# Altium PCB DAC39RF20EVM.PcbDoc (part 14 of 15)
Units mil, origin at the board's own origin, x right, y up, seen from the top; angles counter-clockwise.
Board outline 6200 x 2716.54 mil, 16 copper layers (Top Layer, L2 GND, L3 PWR, L4 GND, L5 PWR, L6 GND, L7 SIG, L8 GND, L9 GND, L10 SIG, L11 GND, L12 PWR, L13 GND, L14 PWR, L15 GND, Bottom Layer), stack 76.97 mil thick; 766 components, 495 nets, 3414 pads, 2373 vias.
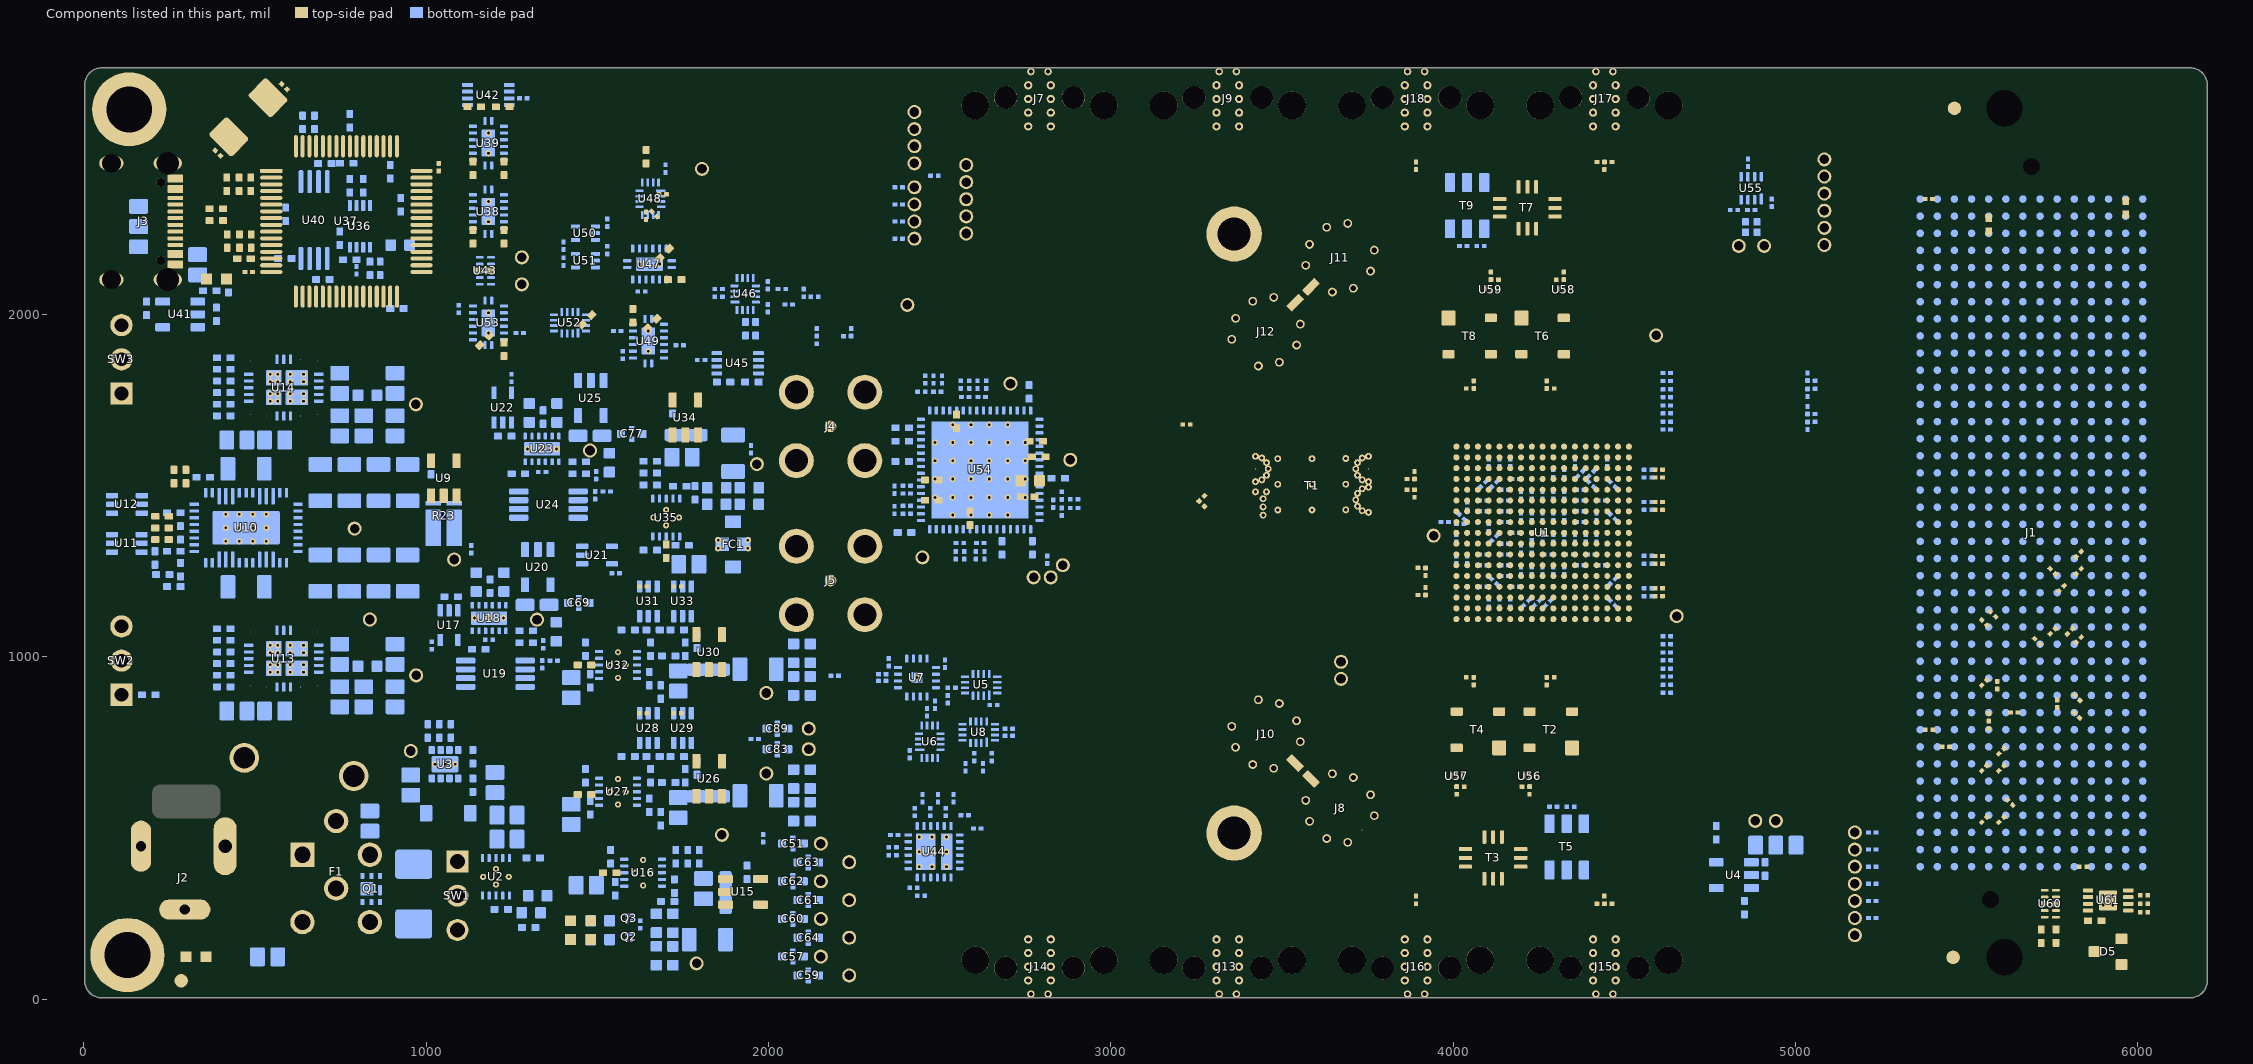
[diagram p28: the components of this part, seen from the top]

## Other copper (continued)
L9 GND:
  pour cut-out: 3434.48,1511.7 ccw(c3422.48,1511.7) 3422.48,1523.7 ccw(c3422.48,1511.7) 3410.48,1511.7 ccw(c3422.48,1511.7) 3422.48,1499.7 ccw(c3422.48,1511.7)
  pour cut-out: 3452.98,1516.66 ccw(c3440.98,1516.66) 3440.98,1528.66 ccw(c3440.98,1516.66) 3428.98,1516.66 ccw(c3440.98,1516.66) 3440.98,1504.66 ccw(c3440.98,1516.66)
  pour cut-out: 3466.52,1530.2 ccw(c3454.52,1530.2) 3454.52,1542.2 ccw(c3454.52,1530.2) 3442.52,1530.2 ccw(c3454.52,1530.2) 3454.52,1518.2 ccw(c3454.52,1530.2)
  pour cut-out: 3471.48,1548.7 ccw(c3459.48,1548.7) 3459.48,1560.7 ccw(c3459.48,1548.7) 3447.48,1548.7 ccw(c3459.48,1548.7) 3459.48,1536.7 ccw(c3459.48,1548.7)
  pour cut-out: 3466.52,1567.2 ccw(c3454.52,1567.2) 3454.52,1579.2 ccw(c3454.52,1567.2) 3442.52,1567.2 ccw(c3454.52,1567.2) 3454.52,1555.2 ccw(c3454.52,1567.2)
  pour cut-out: 3452.98,1580.74 ccw(c3440.98,1580.74) 3440.98,1592.74 ccw(c3440.98,1580.74) 3428.98,1580.74 ccw(c3440.98,1580.74) 3440.98,1568.74 ccw(c3440.98,1580.74)
  pour cut-out: 3434.48,1585.7 ccw(c3422.48,1585.7) 3422.48,1597.7 ccw(c3422.48,1585.7) 3410.48,1585.7 ccw(c3422.48,1585.7) 3422.48,1573.7 ccw(c3422.48,1585.7)
  pour cut-out: 3740.48,1495.7 ccw(c3752.48,1495.7) 3752.48,1483.7 ccw(c3752.48,1495.7) 3764.48,1495.7 ccw(c3752.48,1495.7) 3752.48,1507.7 ccw(c3752.48,1495.7)
  pour cut-out: 3721.98,1490.74 ccw(c3733.98,1490.74) 3733.98,1478.74 ccw(c3733.98,1490.74) 3745.98,1490.74 ccw(c3733.98,1490.74) 3733.98,1502.74 ccw(c3733.98,1490.74)
  pour cut-out: 3708.43,1477.2 ccw(c3720.43,1477.2) 3720.43,1465.2 ccw(c3720.43,1477.2) 3732.43,1477.2 ccw(c3720.43,1477.2) 3720.43,1489.2 ccw(c3720.43,1477.2)
  pour cut-out: 3703.48,1458.7 ccw(c3715.48,1458.7) 3715.48,1446.7 ccw(c3715.48,1458.7) 3727.48,1458.7 ccw(c3715.48,1458.7) 3715.48,1470.7 ccw(c3715.48,1458.7)
  pour cut-out: 3708.43,1440.2 ccw(c3720.43,1440.2) 3720.43,1428.2 ccw(c3720.43,1440.2) 3732.43,1440.2 ccw(c3720.43,1440.2) 3720.43,1452.2 ccw(c3720.43,1440.2)
  pour cut-out: 3721.98,1426.66 ccw(c3733.98,1426.66) 3733.98,1414.66 ccw(c3733.98,1426.66) 3745.98,1426.66 ccw(c3733.98,1426.66) 3733.98,1438.66 ccw(c3733.98,1426.66)
  pour cut-out: 3740.48,1421.7 ccw(c3752.48,1421.7) 3752.48,1409.7 ccw(c3752.48,1421.7) 3764.48,1421.7 ccw(c3752.48,1421.7) 3752.48,1433.7 ccw(c3752.48,1421.7)
  pour cut-out: 3740.48,1511.7 ccw(c3752.48,1511.7) 3752.48,1499.7 ccw(c3752.48,1511.7) 3764.48,1511.7 ccw(c3752.48,1511.7) 3752.48,1523.7 ccw(c3752.48,1511.7)
  pour cut-out: 3721.98,1516.66 ccw(c3733.98,1516.66) 3733.98,1504.66 ccw(c3733.98,1516.66) 3745.98,1516.66 ccw(c3733.98,1516.66) 3733.98,1528.66 ccw(c3733.98,1516.66)
  pour cut-out: 3708.43,1530.2 ccw(c3720.43,1530.2) 3720.43,1518.2 ccw(c3720.43,1530.2) 3732.43,1530.2 ccw(c3720.43,1530.2) 3720.43,1542.2 ccw(c3720.43,1530.2)
  pour cut-out: 3703.48,1548.7 ccw(c3715.48,1548.7) 3715.48,1536.7 ccw(c3715.48,1548.7) 3727.48,1548.7 ccw(c3715.48,1548.7) 3715.48,1560.7 ccw(c3715.48,1548.7)
  pour cut-out: 3708.43,1567.2 ccw(c3720.43,1567.2) 3720.43,1555.2 ccw(c3720.43,1567.2) 3732.43,1567.2 ccw(c3720.43,1567.2) 3720.43,1579.2 ccw(c3720.43,1567.2)
  pour cut-out: 3721.98,1580.74 ccw(c3733.98,1580.74) 3733.98,1568.74 ccw(c3733.98,1580.74) 3745.98,1580.74 ccw(c3733.98,1580.74) 3733.98,1592.74 ccw(c3733.98,1580.74)
  pour cut-out: 3740.48,1585.7 ccw(c3752.48,1585.7) 3752.48,1573.7 ccw(c3752.48,1585.7) 3764.48,1585.7 ccw(c3752.48,1585.7) 3752.48,1597.7 ccw(c3752.48,1585.7)
  pour cut-out: 3998.03,1456.46 ccw(c4009.03,1456.46) 4009.03,1445.46 ccw(c4009.03,1456.46) 4020.03,1456.46 ccw(c4009.03,1456.46) 4009.03,1467.46 ccw(c4009.03,1456.46)
  pour cut-out: 4029.52,1487.95 ccw(c4040.52,1487.95) 4040.52,1476.95 ccw(c4040.52,1487.95) 4051.52,1487.95 ccw(c4040.52,1487.95) 4040.52,1498.95 ccw(c4040.52,1487.95)
  pour cut-out: 4029.52,1519.45 ccw(c4040.52,1519.45) 4040.52,1508.45 ccw(c4040.52,1519.45) 4051.52,1519.45 ccw(c4040.52,1519.45) 4040.52,1530.45 ccw(c4040.52,1519.45)
  pour cut-out: 3998.03,1550.94 ccw(c4009.03,1550.94) 4009.03,1539.94 ccw(c4009.03,1550.94) 4020.03,1550.94 ccw(c4009.03,1550.94) 4009.03,1561.94 ccw(c4009.03,1550.94)
  pour cut-out: 4218.5,1613.94 ccw(c4229.5,1613.94) 4229.5,1602.94 ccw(c4229.5,1613.94) 4240.5,1613.94 ccw(c4229.5,1613.94) 4229.5,1624.94 ccw(c4229.5,1613.94)
  pour cut-out: 4155.51,1613.94 ccw(c4166.51,1613.94) 4166.51,1602.94 ccw(c4166.51,1613.94) 4177.51,1613.94 ccw(c4166.51,1613.94) 4166.51,1624.94 ccw(c4166.51,1613.94)
  pour cut-out: 4092.52,1613.94 ccw(c4103.52,1613.94) 4103.52,1602.94 ccw(c4103.52,1613.94) 4114.52,1613.94 ccw(c4103.52,1613.94) 4103.52,1624.94 ccw(c4103.52,1613.94)
  pour cut-out: 4218.5,1110 ccw(c4229.5,1110) 4229.5,1099 ccw(c4229.5,1110) 4240.5,1110 ccw(c4229.5,1110) 4229.5,1121 ccw(c4229.5,1110)
  pour cut-out: 4155.51,1110 ccw(c4166.51,1110) 4166.51,1099 ccw(c4166.51,1110) 4177.51,1110 ccw(c4166.51,1110) 4166.51,1121 ccw(c4166.51,1110)
  pour cut-out: 4092.52,1110 ccw(c4103.52,1110) 4103.52,1099 ccw(c4103.52,1110) 4114.52,1110 ccw(c4103.52,1110) 4103.52,1121 ccw(c4103.52,1110)
  pour cut-out: 4408.51,157.8 cw(c4408.51,174.8) 4391.51,174.8 cw(c4408.51,174.8) 4408.51,191.8 cw(c4408.51,174.8) 4425.51,174.8 cw(c4408.51,174.8)
  pour cut-out: 4408.51,117.8 cw(c4408.51,134.8) 4391.51,134.8 cw(c4408.51,134.8) 4408.51,151.8 cw(c4408.51,134.8) 4425.51,134.8 cw(c4408.51,134.8)
  pour cut-out: 4408.51,77.8 cw(c4408.51,94.8) 4391.51,94.8 cw(c4408.51,94.8) 4408.51,111.8 cw(c4408.51,94.8) 4425.51,94.8 cw(c4408.51,94.8)
  pour cut-out: 4408.51,37.8 cw(c4408.51,54.8) 4391.51,54.8 cw(c4408.51,54.8) 4408.51,71.8 cw(c4408.51,54.8) 4425.51,54.8 cw(c4408.51,54.8)
  pour cut-out: 4416.51,-2.2 cw(c4416.51,14.8) 4399.51,14.8 cw(c4416.51,14.8) 4416.51,31.8 cw(c4416.51,14.8) 4433.51,14.8 cw(c4416.51,14.8)
  pour cut-out: 4466.51,-2.2 cw(c4466.51,14.8) 4449.51,14.8 cw(c4466.51,14.8) 4466.51,31.8 cw(c4466.51,14.8) 4483.51,14.8 cw(c4466.51,14.8)
  pour cut-out: 4474.51,37.8 cw(c4474.51,54.8) 4457.51,54.8 cw(c4474.51,54.8) 4474.51,71.8 cw(c4474.51,54.8) 4491.51,54.8 cw(c4474.51,54.8)
  pour cut-out: 4474.51,77.8 cw(c4474.51,94.8) 4457.51,94.8 cw(c4474.51,94.8) 4474.51,111.8 cw(c4474.51,94.8) 4491.51,94.8 cw(c4474.51,94.8)
  pour cut-out: 4474.51,157.8 cw(c4474.51,174.8) 4457.51,174.8 cw(c4474.51,174.8) 4474.51,191.8 cw(c4474.51,174.8) 4491.51,174.8 cw(c4474.51,174.8)
  pour cut-out: 4474.51,117.8 cw(c4474.51,134.8) 4457.51,134.8 cw(c4474.51,134.8) 4474.51,151.8 cw(c4474.51,134.8) 4491.51,134.8 cw(c4474.51,134.8)
  pour cut-out: 3858.51,157.8 cw(c3858.51,174.8) 3841.51,174.8 cw(c3858.51,174.8) 3858.51,191.8 cw(c3858.51,174.8) 3875.51,174.8 cw(c3858.51,174.8)
  pour cut-out: 3858.51,117.8 cw(c3858.51,134.8) 3841.51,134.8 cw(c3858.51,134.8) 3858.51,151.8 cw(c3858.51,134.8) 3875.51,134.8 cw(c3858.51,134.8)
  pour cut-out: 3858.51,77.8 cw(c3858.51,94.8) 3841.51,94.8 cw(c3858.51,94.8) 3858.51,111.8 cw(c3858.51,94.8) 3875.51,94.8 cw(c3858.51,94.8)
  pour cut-out: 3858.51,37.8 cw(c3858.51,54.8) 3841.51,54.8 cw(c3858.51,54.8) 3858.51,71.8 cw(c3858.51,54.8) 3875.51,54.8 cw(c3858.51,54.8)
  pour cut-out: 3866.51,-2.2 cw(c3866.51,14.8) 3849.51,14.8 cw(c3866.51,14.8) 3866.51,31.8 cw(c3866.51,14.8) 3883.51,14.8 cw(c3866.51,14.8)
  pour cut-out: 3916.51,-2.2 cw(c3916.51,14.8) 3899.51,14.8 cw(c3916.51,14.8) 3916.51,31.8 cw(c3916.51,14.8) 3933.51,14.8 cw(c3916.51,14.8)
  pour cut-out: 3924.51,37.8 cw(c3924.51,54.8) 3907.51,54.8 cw(c3924.51,54.8) 3924.51,71.8 cw(c3924.51,54.8) 3941.51,54.8 cw(c3924.51,54.8)
  pour cut-out: 3924.51,77.8 cw(c3924.51,94.8) 3907.51,94.8 cw(c3924.51,94.8) 3924.51,111.8 cw(c3924.51,94.8) 3941.51,94.8 cw(c3924.51,94.8)
  pour cut-out: 3924.51,157.8 cw(c3924.51,174.8) 3907.51,174.8 cw(c3924.51,174.8) 3924.51,191.8 cw(c3924.51,174.8) 3941.51,174.8 cw(c3924.51,174.8)
  pour cut-out: 3924.51,117.8 cw(c3924.51,134.8) 3907.51,134.8 cw(c3924.51,134.8) 3924.51,151.8 cw(c3924.51,134.8) 3941.51,134.8 cw(c3924.51,134.8)
  pour cut-out: 3308.51,157.8 cw(c3308.51,174.8) 3291.51,174.8 cw(c3308.51,174.8) 3308.51,191.8 cw(c3308.51,174.8) 3325.51,174.8 cw(c3308.51,174.8)
  pour cut-out: 3308.51,117.8 cw(c3308.51,134.8) 3291.51,134.8 cw(c3308.51,134.8) 3308.51,151.8 cw(c3308.51,134.8) 3325.51,134.8 cw(c3308.51,134.8)
  pour cut-out: 3308.51,77.8 cw(c3308.51,94.8) 3291.51,94.8 cw(c3308.51,94.8) 3308.51,111.8 cw(c3308.51,94.8) 3325.51,94.8 cw(c3308.51,94.8)
  pour cut-out: 3308.51,37.8 cw(c3308.51,54.8) 3291.51,54.8 cw(c3308.51,54.8) 3308.51,71.8 cw(c3308.51,54.8) 3325.51,54.8 cw(c3308.51,54.8)
  pour cut-out: 3316.51,-2.2 cw(c3316.51,14.8) 3299.51,14.8 cw(c3316.51,14.8) 3316.51,31.8 cw(c3316.51,14.8) 3333.51,14.8 cw(c3316.51,14.8)
  pour cut-out: 3366.51,-2.2 cw(c3366.51,14.8) 3349.51,14.8 cw(c3366.51,14.8) 3366.51,31.8 cw(c3366.51,14.8) 3383.51,14.8 cw(c3366.51,14.8)
  pour cut-out: 3374.51,37.8 cw(c3374.51,54.8) 3357.51,54.8 cw(c3374.51,54.8) 3374.51,71.8 cw(c3374.51,54.8) 3391.51,54.8 cw(c3374.51,54.8)
  pour cut-out: 3374.51,77.8 cw(c3374.51,94.8) 3357.51,94.8 cw(c3374.51,94.8) 3374.51,111.8 cw(c3374.51,94.8) 3391.51,94.8 cw(c3374.51,94.8)
  pour cut-out: 3374.51,157.8 cw(c3374.51,174.8) 3357.51,174.8 cw(c3374.51,174.8) 3374.51,191.8 cw(c3374.51,174.8) 3391.51,174.8 cw(c3374.51,174.8)
  pour cut-out: 3374.51,117.8 cw(c3374.51,134.8) 3357.51,134.8 cw(c3374.51,134.8) 3374.51,151.8 cw(c3374.51,134.8) 3391.51,134.8 cw(c3374.51,134.8)
  pour cut-out: 2758.51,157.8 cw(c2758.51,174.8) 2741.51,174.8 cw(c2758.51,174.8) 2758.51,191.8 cw(c2758.51,174.8) 2775.51,174.8 cw(c2758.51,174.8)
  pour cut-out: 2758.51,117.8 cw(c2758.51,134.8) 2741.51,134.8 cw(c2758.51,134.8) 2758.51,151.8 cw(c2758.51,134.8) 2775.51,134.8 cw(c2758.51,134.8)
  pour cut-out: 2758.51,77.8 cw(c2758.51,94.8) 2741.51,94.8 cw(c2758.51,94.8) 2758.51,111.8 cw(c2758.51,94.8) 2775.51,94.8 cw(c2758.51,94.8)
  pour cut-out: 2758.51,37.8 cw(c2758.51,54.8) 2741.51,54.8 cw(c2758.51,54.8) 2758.51,71.8 cw(c2758.51,54.8) 2775.51,54.8 cw(c2758.51,54.8)
  pour cut-out: 2766.51,-2.2 cw(c2766.51,14.8) 2749.51,14.8 cw(c2766.51,14.8) 2766.51,31.8 cw(c2766.51,14.8) 2783.51,14.8 cw(c2766.51,14.8)
  pour cut-out: 2816.51,-2.2 cw(c2816.51,14.8) 2799.51,14.8 cw(c2816.51,14.8) 2816.51,31.8 cw(c2816.51,14.8) 2833.51,14.8 cw(c2816.51,14.8)
  pour cut-out: 2824.51,37.8 cw(c2824.51,54.8) 2807.51,54.8 cw(c2824.51,54.8) 2824.51,71.8 cw(c2824.51,54.8) 2841.51,54.8 cw(c2824.51,54.8)
  pour cut-out: 2824.51,77.8 cw(c2824.51,94.8) 2807.51,94.8 cw(c2824.51,94.8) 2824.51,111.8 cw(c2824.51,94.8) 2841.51,94.8 cw(c2824.51,94.8)
  pour cut-out: 2824.51,157.8 cw(c2824.51,174.8) 2807.51,174.8 cw(c2824.51,174.8) 2824.51,191.8 cw(c2824.51,174.8) 2841.51,174.8 cw(c2824.51,174.8)
  pour cut-out: 2824.51,117.8 cw(c2824.51,134.8) 2807.51,134.8 cw(c2824.51,134.8) 2824.51,151.8 cw(c2824.51,134.8) 2841.51,134.8 cw(c2824.51,134.8)
  pour cut-out: 2824.51,2566.14 cw(c2824.51,2549.14) 2841.51,2549.14 cw(c2824.51,2549.14) 2824.51,2532.14 cw(c2824.51,2549.14) 2807.51,2549.14 cw(c2824.51,2549.14)
  pour cut-out: 2824.51,2606.14 cw(c2824.51,2589.14) 2841.51,2589.14 cw(c2824.51,2589.14) 2824.51,2572.14 cw(c2824.51,2589.14) 2807.51,2589.14 cw(c2824.51,2589.14)
  pour cut-out: 2824.51,2646.14 cw(c2824.51,2629.14) 2841.51,2629.14 cw(c2824.51,2629.14) 2824.51,2612.14 cw(c2824.51,2629.14) 2807.51,2629.14 cw(c2824.51,2629.14)
  pour cut-out: 2824.51,2686.14 cw(c2824.51,2669.14) 2841.51,2669.14 cw(c2824.51,2669.14) 2824.51,2652.14 cw(c2824.51,2669.14) 2807.51,2669.14 cw(c2824.51,2669.14)
  pour cut-out: 2816.51,2726.14 cw(c2816.51,2709.14) 2833.51,2709.14 cw(c2816.51,2709.14) 2816.51,2692.14 cw(c2816.51,2709.14) 2799.51,2709.14 cw(c2816.51,2709.14)
  pour cut-out: 2766.51,2726.14 cw(c2766.51,2709.14) 2783.51,2709.14 cw(c2766.51,2709.14) 2766.51,2692.14 cw(c2766.51,2709.14) 2749.51,2709.14 cw(c2766.51,2709.14)
  pour cut-out: 2758.51,2686.14 cw(c2758.51,2669.14) 2775.51,2669.14 cw(c2758.51,2669.14) 2758.51,2652.14 cw(c2758.51,2669.14) 2741.51,2669.14 cw(c2758.51,2669.14)
  pour cut-out: 2758.51,2646.14 cw(c2758.51,2629.14) 2775.51,2629.14 cw(c2758.51,2629.14) 2758.51,2612.14 cw(c2758.51,2629.14) 2741.51,2629.14 cw(c2758.51,2629.14)
  pour cut-out: 2758.51,2566.14 cw(c2758.51,2549.14) 2775.51,2549.14 cw(c2758.51,2549.14) 2758.51,2532.14 cw(c2758.51,2549.14) 2741.51,2549.14 cw(c2758.51,2549.14)
  pour cut-out: 2758.51,2606.14 cw(c2758.51,2589.14) 2775.51,2589.14 cw(c2758.51,2589.14) 2758.51,2572.14 cw(c2758.51,2589.14) 2741.51,2589.14 cw(c2758.51,2589.14)
  pour cut-out: 3374.51,2566.14 cw(c3374.51,2549.14) 3391.51,2549.14 cw(c3374.51,2549.14) 3374.51,2532.14 cw(c3374.51,2549.14) 3357.51,2549.14 cw(c3374.51,2549.14)
  pour cut-out: 3374.51,2606.14 cw(c3374.51,2589.14) 3391.51,2589.14 cw(c3374.51,2589.14) 3374.51,2572.14 cw(c3374.51,2589.14) 3357.51,2589.14 cw(c3374.51,2589.14)
  pour cut-out: 3374.51,2646.14 cw(c3374.51,2629.14) 3391.51,2629.14 cw(c3374.51,2629.14) 3374.51,2612.14 cw(c3374.51,2629.14) 3357.51,2629.14 cw(c3374.51,2629.14)
  pour cut-out: 3374.51,2686.14 cw(c3374.51,2669.14) 3391.51,2669.14 cw(c3374.51,2669.14) 3374.51,2652.14 cw(c3374.51,2669.14) 3357.51,2669.14 cw(c3374.51,2669.14)
  pour cut-out: 3366.51,2726.14 cw(c3366.51,2709.14) 3383.51,2709.14 cw(c3366.51,2709.14) 3366.51,2692.14 cw(c3366.51,2709.14) 3349.51,2709.14 cw(c3366.51,2709.14)
  pour cut-out: 3316.51,2726.14 cw(c3316.51,2709.14) 3333.51,2709.14 cw(c3316.51,2709.14) 3316.51,2692.14 cw(c3316.51,2709.14) 3299.51,2709.14 cw(c3316.51,2709.14)
  pour cut-out: 3308.51,2686.14 cw(c3308.51,2669.14) 3325.51,2669.14 cw(c3308.51,2669.14) 3308.51,2652.14 cw(c3308.51,2669.14) 3291.51,2669.14 cw(c3308.51,2669.14)
  pour cut-out: 3308.51,2646.14 cw(c3308.51,2629.14) 3325.51,2629.14 cw(c3308.51,2629.14) 3308.51,2612.14 cw(c3308.51,2629.14) 3291.51,2629.14 cw(c3308.51,2629.14)
  pour cut-out: 3308.51,2566.14 cw(c3308.51,2549.14) 3325.51,2549.14 cw(c3308.51,2549.14) 3308.51,2532.14 cw(c3308.51,2549.14) 3291.51,2549.14 cw(c3308.51,2549.14)
  pour cut-out: 3308.51,2606.14 cw(c3308.51,2589.14) 3325.51,2589.14 cw(c3308.51,2589.14) 3308.51,2572.14 cw(c3308.51,2589.14) 3291.51,2589.14 cw(c3308.51,2589.14)
  pour cut-out: 3924.51,2566.14 cw(c3924.51,2549.14) 3941.51,2549.14 cw(c3924.51,2549.14) 3924.51,2532.14 cw(c3924.51,2549.14) 3907.51,2549.14 cw(c3924.51,2549.14)
  pour cut-out: 3924.51,2606.14 cw(c3924.51,2589.14) 3941.51,2589.14 cw(c3924.51,2589.14) 3924.51,2572.14 cw(c3924.51,2589.14) 3907.51,2589.14 cw(c3924.51,2589.14)
  pour cut-out: 3924.51,2646.14 cw(c3924.51,2629.14) 3941.51,2629.14 cw(c3924.51,2629.14) 3924.51,2612.14 cw(c3924.51,2629.14) 3907.51,2629.14 cw(c3924.51,2629.14)
  pour cut-out: 3924.51,2686.14 cw(c3924.51,2669.14) 3941.51,2669.14 cw(c3924.51,2669.14) 3924.51,2652.14 cw(c3924.51,2669.14) 3907.51,2669.14 cw(c3924.51,2669.14)
  pour cut-out: 3916.51,2726.14 cw(c3916.51,2709.14) 3933.51,2709.14 cw(c3916.51,2709.14) 3916.51,2692.14 cw(c3916.51,2709.14) 3899.51,2709.14 cw(c3916.51,2709.14)
  pour cut-out: 3866.51,2726.14 cw(c3866.51,2709.14) 3883.51,2709.14 cw(c3866.51,2709.14) 3866.51,2692.14 cw(c3866.51,2709.14) 3849.51,2709.14 cw(c3866.51,2709.14)
  pour cut-out: 3858.51,2686.14 cw(c3858.51,2669.14) 3875.51,2669.14 cw(c3858.51,2669.14) 3858.51,2652.14 cw(c3858.51,2669.14) 3841.51,2669.14 cw(c3858.51,2669.14)
  pour cut-out: 3858.51,2646.14 cw(c3858.51,2629.14) 3875.51,2629.14 cw(c3858.51,2629.14) 3858.51,2612.14 cw(c3858.51,2629.14) 3841.51,2629.14 cw(c3858.51,2629.14)
  pour cut-out: 3858.51,2566.14 cw(c3858.51,2549.14) 3875.51,2549.14 cw(c3858.51,2549.14) 3858.51,2532.14 cw(c3858.51,2549.14) 3841.51,2549.14 cw(c3858.51,2549.14)
  pour cut-out: 3858.51,2606.14 cw(c3858.51,2589.14) 3875.51,2589.14 cw(c3858.51,2589.14) 3858.51,2572.14 cw(c3858.51,2589.14) 3841.51,2589.14 cw(c3858.51,2589.14)
  pour cut-out: 4408.51,2606.14 cw(c4408.51,2589.14) 4425.51,2589.14 cw(c4408.51,2589.14) 4408.51,2572.14 cw(c4408.51,2589.14) 4391.51,2589.14 cw(c4408.51,2589.14)
  pour cut-out: 4408.51,2566.14 cw(c4408.51,2549.14) 4425.51,2549.14 cw(c4408.51,2549.14) 4408.51,2532.14 cw(c4408.51,2549.14) 4391.51,2549.14 cw(c4408.51,2549.14)
  pour cut-out: 4408.51,2646.14 cw(c4408.51,2629.14) 4425.51,2629.14 cw(c4408.51,2629.14) 4408.51,2612.14 cw(c4408.51,2629.14) 4391.51,2629.14 cw(c4408.51,2629.14)
  pour cut-out: 4408.51,2686.14 cw(c4408.51,2669.14) 4425.51,2669.14 cw(c4408.51,2669.14) 4408.51,2652.14 cw(c4408.51,2669.14) 4391.51,2669.14 cw(c4408.51,2669.14)
  pour cut-out: 4416.51,2726.14 cw(c4416.51,2709.14) 4433.51,2709.14 cw(c4416.51,2709.14) 4416.51,2692.14 cw(c4416.51,2709.14) 4399.51,2709.14 cw(c4416.51,2709.14)
  pour cut-out: 4466.51,2726.14 cw(c4466.51,2709.14) 4483.51,2709.14 cw(c4466.51,2709.14) 4466.51,2692.14 cw(c4466.51,2709.14) 4449.51,2709.14 cw(c4466.51,2709.14)
  pour cut-out: 4474.51,2686.14 cw(c4474.51,2669.14) 4491.51,2669.14 cw(c4474.51,2669.14) 4474.51,2652.14 cw(c4474.51,2669.14) 4457.51,2669.14 cw(c4474.51,2669.14)
  pour cut-out: 4474.51,2646.14 cw(c4474.51,2629.14) 4491.51,2629.14 cw(c4474.51,2629.14) 4474.51,2612.14 cw(c4474.51,2629.14) 4457.51,2629.14 cw(c4474.51,2629.14)
  pour cut-out: 4474.51,2606.14 cw(c4474.51,2589.14) 4491.51,2589.14 cw(c4474.51,2589.14) 4474.51,2572.14 cw(c4474.51,2589.14) 4457.51,2589.14 cw(c4474.51,2589.14)
  pour cut-out: 4474.51,2566.14 cw(c4474.51,2549.14) 4491.51,2549.14 cw(c4474.51,2549.14) 4474.51,2532.14 cw(c4474.51,2549.14) 4457.51,2549.14 cw(c4474.51,2549.14)
  text ".Layer_Name" at 573,-856.23 h60
L10 SIG:
  drawing of 348 lines, arcs and shapes, not listed
  text ".Layer_Name" at 573,-856.23 h60
Bottom Layer:
  drawing of 359 lines, arcs and shapes, not listed
  text ".Layer_Name" at 579.59,-854.69 h60
Multi-Layer:
  pour cut-out: 342.52,1360.55 ccw(c342.52,1347.06) 329.03,1347.06 ccw(c342.52,1347.06) 342.52,1333.58 ccw(c342.52,1347.06) 356.01,1347.06 ccw(c342.52,1347.06)
  pour cut-out: 4279.49,1110 cw(c4292.49,1110) 4292.49,1123 4323.49,1123 cw(c4323.49,1110) 4336.49,1110 cw(c4323.49,1110) 4323.49,1097 4292.49,1097 cw(c4292.49,1110)
  pour cut-out: 4279.49,1141.5 cw(c4292.49,1141.5) 4292.49,1154.5 4323.49,1154.5 cw(c4323.49,1141.5) 4336.49,1141.5 cw(c4323.49,1141.5) 4323.49,1128.5 4292.49,1128.5 cw(c4292.49,1141.5)
  pour cut-out: 4373.98,1110 cw(c4386.98,1110) 4386.98,1123 4417.98,1123 cw(c4417.98,1110) 4430.98,1110 cw(c4417.98,1110) 4417.98,1097 4386.98,1097 cw(c4386.98,1110)
  pour cut-out: 4373.98,1141.5 cw(c4386.98,1141.5) 4386.98,1154.5 4417.98,1154.5 cw(c4417.98,1141.5) 4430.98,1141.5 cw(c4417.98,1141.5) 4417.98,1128.5 4386.98,1128.5 cw(c4386.98,1141.5)
  pour cut-out: 4481.47,1217.49 cw(c4481.47,1204.49) 4494.47,1204.49 4494.47,1173.49 cw(c4481.47,1173.49) 4481.47,1160.49 cw(c4481.47,1173.49) 4468.47,1173.49 4468.47,1204.49 cw(c4481.47,1204.49)
  pour cut-out: 4481.47,1311.98 cw(c4481.47,1298.98) 4494.47,1298.98 4494.47,1267.98 cw(c4481.47,1267.98) 4481.47,1254.98 cw(c4481.47,1267.98) 4468.47,1267.98 4468.47,1298.98 cw(c4481.47,1298.98)
  pour cut-out: 4481.47,1469.46 cw(c4481.47,1456.46) 4494.47,1456.46 4494.47,1425.46 cw(c4481.47,1425.46) 4481.47,1412.46 cw(c4481.47,1425.46) 4468.47,1425.46 4468.47,1456.46 cw(c4481.47,1456.46)
  pour cut-out: 4481.47,1563.94 cw(c4481.47,1550.94) 4494.47,1550.94 4494.47,1519.94 cw(c4481.47,1519.94) 4481.47,1506.94 cw(c4481.47,1519.94) 4468.47,1519.94 4468.47,1550.94 cw(c4481.47,1550.94)
  pour cut-out: 4431.48,1582.44 cw(c4418.48,1582.44) 4418.48,1569.44 4387.48,1569.44 cw(c4387.48,1582.44) 4374.48,1582.44 cw(c4387.48,1582.44) 4387.48,1595.44 4418.48,1595.44 cw(c4418.48,1582.44)
  pour cut-out: 4336.99,1582.44 cw(c4323.99,1582.44) 4323.99,1569.44 4292.99,1569.44 cw(c4292.99,1582.44) 4279.99,1582.44 cw(c4292.99,1582.44) 4292.99,1595.44 4323.99,1595.44 cw(c4323.99,1582.44)
  pour cut-out: 4336.99,1613.94 cw(c4323.99,1613.94) 4323.99,1600.94 4292.99,1600.94 cw(c4292.99,1613.94) 4279.99,1613.94 cw(c4292.99,1613.94) 4292.99,1626.94 4323.99,1626.94 cw(c4323.99,1613.94)
  pour cut-out: 4431.48,1613.94 cw(c4418.48,1613.94) 4418.48,1600.94 4387.48,1600.94 cw(c4387.48,1613.94) 4374.48,1613.94 cw(c4387.48,1613.94) 4387.48,1626.94 4418.48,1626.94 cw(c4418.48,1613.94)

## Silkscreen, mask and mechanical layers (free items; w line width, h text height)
Top Overlay:
  lines w5: 5577.59,613.8 5582.59,613.8 ; 5947.59,1343.8 6037.59,1343.8
  lines w6: 2317.61,2193.8 2267.61,2193.8 2267.61,2393.8 2317.61,2393.8 ; 2317.61,2413.8 2267.61,2413.8 2267.61,2613.8 2317.61,2613.8 ; 2337.61,2293.8 2387.61,2293.8 ; 2337.61,2513.8 2387.61,2513.8 ; 2587.61,2203.8 2537.61,2203.8 2537.61,2463.8 2587.61,2463.8 ; 2609.61,2356.8 2726.61,2356.8 ; 2609.61,2406.8 2701.61,2406.8 ; 5095.61,2172.8 5045.61,2172.8 5045.61,2482.8 5095.61,2482.8 ; 5185.61,156.13 5135.61,156.13 5135.61,516.13 5185.61,516.13 ; 5237.61,2428.8 5287.61,2428.8 ; 5237.61,2478.8 5287.61,2478.8
  lines w7: 457.61,2443.8 457.61,2423.8 ; 477.61,2423.8 457.61,2423.8 ; 5752.61,1682.59 5752.61,1703.8 ; 5773.82,1703.8 5752.61,1703.8 ; 5862.61,1063.8 5847.61,1078.8 ; 5862.61,1093.8 5847.61,1078.8 ; 5877.61,1348.8 5862.61,1363.8 ; 5877.61,1378.8 5862.61,1363.8 ; 5927.61,1138.8 5867.61,1078.8 5847.61,1078.8 ; 5927.61,1363.8 5862.61,1363.8 ; 6002.61,1453.8 5752.61,1703.8 ; 457.61,2423.8 637.61,2603.8 687.61,2603.8 ; 687.61,2603.8 687.61,2568.8 807.61,2568.8 807.61,2673.8 687.61,2673.8 687.61,2603.8 ; 2365,1955 2365,2060 2680,2060 2680,1955 2365,1955 ; 2673.16,1727.32 2828.78,1727.32 2828.78,1828.68 2673.16,1828.68 2673.16,1727.32 ; 2718.13,1142.28 2718.13,1356.65 2981.55,1356.65 2981.55,1142.28 2718.13,1142.28 ; 2849.84,1503.46 2849.84,1604.83 3035.05,1604.83 3035.05,1503.46 2849.84,1503.46 ; 4846.94,429.21 4970.99,429.21 4970.99,649.04 4846.94,649.04 4846.94,429.21 ; 5937.61,1098.8 6172.61,1098.8 6172.61,1273.8 6172.61,1433.8 5937.61,1433.8 5937.61,1273.8 5937.61,1098.8
  text "FTDI / FPGA / CTRL" at 2267.61,2458.8 h55 r90
  text "FMC" at 5035.2,2295.65 h55 r90
  text "2GHz / TO / 18GHz" at 3984.61,2241.1 h30
  text "FTDI DAC" at 2267.61,2237.38 h55 r90
  text "FTDI DAC" at 2537.61,2229.27 h55 r90
  text "LMK" at 2364.03,1953 h55
  text "LMK" at 2673.16,1724.4 h55
  text "RESET" at 5642.61,1723.8 h25
  text "LMK" at 2849.84,1500.54 h55
  text "FTDI-FPGA" at 5937.61,1393.8 h55
  text "CCLK" at 6012.61,1363.8 h25
  text "PROG" at 5947.61,1308.8 h25
  text "LMK" at 2718.13,1304.41 h55
  text "DONE" at 6012.61,1273.8 h25
  text "DIN" at 6097.61,1243.8 h25
  text "SCLK" at 5945.97,1143.8 h25
  text "SDI" at 6100.94,1143.8 h25
  text "SEN" at 5945.96,1108.8 h25
  text "SDO" at 6092.61,1108.8 h25
  text "DAC39RF20EVM / Rev E1" at 2358.39,836.81 h60
  text "FAN" at 4846.94,429.21 h80
  text "2GHz / TO / 18GHz" at 4227.85,353.11 h30
  text "DAC" at 5125.2,301.57 h55 r90
  text "POWER / FAULT" at 1380.88,24.8 h80
  text ".Layer_Name" at 579.59,-854.69 h60
Board Layer Stack Bottom Overlay:
  region: 1667.61,618.8 1667.61,608.8 1677.61,618.8
  lines w6: 2345.61,2511.8 2395.61,2511.8 ; 2457.61,2243.8 2507.61,2243.8 ; 2615.61,2412.8 2725.61,2412.8 ; 2616.61,2362.8 2755.61,2362.8 ; 2892.61,1288.8 2942.61,1288.8 ; 5112.61,2428.8 5162.61,2428.8 ; 5112.61,2478.8 5162.61,2478.8
  lines w7: 190,2165 295,2165 ; 315,2205 315,2380 ; 827.61,2433.8 827.61,2413.8 ; 847.61,2413.8 827.61,2413.8 ; 862.61,2448.8 827.61,2413.8 ; 1592.61,118.8 1612.61,118.8 1642.61,148.8 ; 1622.61,148.8 1642.61,148.8 ; 1642.61,128.8 1642.61,148.8 ; 2937.61,1433.8 2922.61,1448.8 ; 2937.61,1463.8 2922.61,1448.8 ; 2987.61,1543.8 2987.61,1478.8 2957.61,1448.8 2922.61,1448.8 ; 5075,355 5075,405 5140,470 ; 5120,470 5140,470 ; 5140,450 5140,470 ; 5255,440 5255,465 ; 5280,465 5255,465 ; 5295,255 5280,270 5280,440 5255,465 ; 2085,1840 2155,1840 2195,1880 2295,1880 2295,1920 2390,1920 2390,1990 2295,1990 2295,2030 2170,2030 2085,1945 2085,1840
  lines w10: 3032.61,1033.8 3232.61,833.8 4282.61,833.8 4512.61,1063.8 4512.61,1658.8 3237.61,1658.8 3202.61,1623.8 3032.61,1453.8 3032.61,1033.8
  text "3p3V" at 307.6,2344.92 h60
  text "UTIL" at 301.6,2294.8 h30
  text "5MHz TO 10GHz" at 3950,2250 h30
  text "FTDI" at 296.6,2239.8 h30
  text "LDO" at 276.61,2179.8 h30
  text "DAC SYNC" at 2391,1920 h50
  text "12V" at 5104,456 h30
  text "5V" at 4849,441 h30
  text "5MHz TO 10GHz" at 4555,380 h30
  text ".Layer_Name" at 579.59,-854.69 h60
Top Paste:
  text ".Layer_Name" at 579.59,-854.69 h60
Bottom Paste:
  text ".Layer_Name" at 579.59,-854.69 h60
Top Solder:
  drawing of 41 lines, arcs and shapes, not listed
  text ".Layer_Name" at 579.59,-854.69 h60
  text ".Layer_Name" at 579.59,-854.69 h60
Board Layer Stack Bottom Solder:
  text ".Layer_Name" at 579.59,-854.69 h60
Drill Guide:
  text ".Layer_Name" at 579.59,-854.69 h60
M1 Board Outline:
  lines w5: 2.59,53.8 ccw(c52.59,53.8) 52.59,3.8 102.59,3.8 6152.59,3.8 ccw(c6152.59,53.8) 6202.59,53.8 6202.59,103.8 6202.59,2620.34 6202.59,2670.34 ccw(c6152.59,2670.34) 6152.59,2720.34 102.59,2720.34 52.59,2720.34 ccw(c52.59,2670.34) 2.59,2670.34 2.59,2620.34 2.59,103.8 2.59,53.8
  text ".Layer_Name" at 579.59,-854.69 h60
M2 Board Dimensions:
  rectangle: 127.59,-396.2 502.59,-271.2
  rectangle: 2.59,-271.2 127.59,-146.2
  lines w7: 2.59,-271.2 1002.59,-271.2 ; 127.59,-396.2 127.59,-146.2 ; 252.59,-396.2 252.59,-146.2 ; 502.59,-396.2 502.59,-146.2 ; 752.59,-396.2 752.59,-146.2 ; 2.59,-396.2 2.59,-146.2 1002.59,-146.2 1002.59,-396.2 2.59,-396.2
  text ".Layer_Name" at 579.59,-854.69 h60
M3 3D STEP Top:
  text ".Layer_Name" at 579.59,-854.69 h60
M4 3D STEP Bottom:
  text ".Layer_Name" at 579.59,-854.69 h60
M5 Assembly Top:
  lines w10: -289.41,-926.37 6310.59,-926.37 ; -289.41,-723.03 6312.59,-723.03 ; -289.41,-519.7 -289.41,-1129.7 3715.59,-1129.7 6312.59,-1129.7 6312.59,-519.7 -288.91,-519.7 -288.91,-1129.7 1286.59,-1129.7 ; 2175.59,-1129.7 2175.59,-519.7 ; 3442.59,-723.03 3442.59,-519.7 ; 4282.59,-723.03 4282.59,-519.7 ; 4904.59,-1136.2 4904.59,-933.37
  text "COMPONENTS MARKED 'DNP' SHOULD NOT BE POPULATED." at 1156.09,-314.7 h60
  text "ASSEMBLY VARIANT:" at 1155.59,-430.2 h60
  text ".VariantName" at 2191.59,-430.2 h60
  text "PCB VIEWED FROM TOP SIDE" at -225.91,-651.87 h60
  text "BOARD #:" at 2250.59,-651.87 h60
  text ".PRJ_Number" at 2796.09,-651.87 h60
  text "REV:" at 3640.59,-651.87 h60
  text ".PCB_Rev" at 3932.09,-651.87 h60
  text "SVN REV:" at 4478.59,-651.87 h60
  text ".VersionControl_RevNumber" at 4984.59,-651.87 h60
  text "PLOT NAME =" at -225.91,-1060.54 h60
  text ".plot_File_Name" at 579.59,-1060.54 h60
  text "GENERATED    :" at 2252.59,-1060.54 h60
  text ".Print_Date" at 3122.09,-1060.54 h60
  text ".Print_Time" at 3851.09,-1060.54 h60
  text "TEXAS INSTRUMENTS" at 5115.59,-1060.54 h60
M6 Assembly Bottom:
  lines w10: -289.91,-723.53 6312.09,-723.53 ; -287.91,-926.87 6312.09,-926.87 ; 1118.09,-1136.7 1118.09,-933.87 ; 1740.09,-723.53 1740.09,-520.2 ; 2580.09,-723.53 2580.09,-520.2 ; 3847.09,-1130.2 3847.09,-520.2 ; 4736.09,-1130.2 6311.59,-1130.2 6311.59,-520.2 -289.91,-520.2 -289.91,-1130.2 2307.09,-1130.2 6312.09,-1130.2 6312.09,-520.2
  text "COMPONENTS MARKED 'DNP' SHOULD NOT BE POPULATED." at 6104.59,-314.2 h60
  text ".VariantName" at 5060.59,-430.2 h60
  text "ASSEMBLY VARIANT:" at 6099.59,-430.2 h60
  text ".VersionControl_RevNumber" at 1038.09,-652.37 h60
  text "SVN REV:" at 1544.09,-652.37 h60
  text ".PCB_Rev" at 2090.59,-652.37 h60
  text "REV:" at 2382.09,-652.37 h60
  text ".PRJ_Number" at 3226.59,-652.37 h60
  text "BOARD #:" at 3772.09,-652.37 h60
  text "PCB VIEWED FROM BOTTOM SIDE" at 6248.59,-652.37 h60
  text "TEXAS INSTRUMENTS" at 907.09,-1061.04 h60
  text ".Print_Time" at 2171.59,-1061.04 h60
  text ".Print_Date" at 2900.59,-1061.04 h60
  text "GENERATED    :" at 3770.09,-1061.04 h60
  text ".plot_File_Name" at 5443.09,-1061.04 h60
  text "PLOT NAME =" at 6248.59,-1061.04 h60
M7 Component Dimensions:
  lines w0.1: 3190.14,1653.7 3190.14,1703.7 3210.14,1703.7 3210.14,1653.7 3190.14,1653.7 ; 3229.47,1454.68 3264.83,1490.03 3278.97,1475.89 3243.61,1440.53 3229.47,1454.68 ; 3231.89,1653.7 3231.89,1703.7 3251.89,1703.7 3251.89,1653.7 3231.89,1653.7 ; 3255.64,1421.38 3290.99,1456.74 3305.14,1442.59 3269.78,1407.24 3255.64,1421.38 ; 3255.64,1487.92 3290.99,1452.56 3305.14,1466.7 3269.78,1502.06 3255.64,1487.92 ; 3387.99,1523.7 3387.99,1573.7 3407.99,1573.7 3407.99,1523.7 3387.99,1523.7 ; 3767.7,1523.7 3767.7,1573.7 3787.7,1573.7 3787.7,1523.7 3767.7,1523.7 ; 3767.93,1433.7 3767.93,1483.7 3787.93,1483.7 3787.93,1433.7 3767.93,1433.7 ; 3844.8,1494.45 3844.8,1544.45 3864.8,1544.45 3864.8,1494.45 3844.8,1494.45 ; 3844.92,1462.95 3844.92,1512.95 3864.92,1512.95 3864.92,1462.95 3844.92,1462.95 ; 3861.85,1445.91 3911.85,1445.91 3911.85,1465.91 3861.85,1465.91 3861.85,1445.91 ; 3861.85,1541.5 3911.85,1541.5 3911.85,1561.5 3861.85,1561.5 3861.85,1541.5 ; 3885.2,1465.55 3885.2,1515.55 3905.2,1515.55 3905.2,1465.55 3885.2,1465.55 ; 3885.2,1495.55 3885.2,1545.55 3905.2,1545.55 3905.2,1495.55 3885.2,1495.55 ; 3989.8,1459.45 3989.8,1509.45 4009.8,1509.45 4009.8,1459.45 3989.8,1459.45 ; 3989.8,1494.45 3989.8,1544.45 4009.8,1544.45 4009.8,1494.45 3989.8,1494.45 ; 4085,2046.89 4135,2046.89 4135,2066.89 4085,2066.89 4085,2046.89 ; 4085,2123.63 4135,2123.63 4135,2143.63 4085,2143.63 4085,2123.63 ; 4091.51,321.54 4141.51,321.54 4141.51,351.54 4091.51,351.54 4091.51,321.54 ; 4173,1613.94 4223,1613.94 4223,1633.94 4173,1633.94 4173,1613.94 ; 4217.1,2220.21 4267.1,2220.21 4267.1,2250.21 4217.1,2250.21 4217.1,2220.21 ; 4248.02,1805.98 4298.02,1805.98 4298.02,1825.98 4248.02,1825.98 4248.02,1805.98 ; 4298.02,2046.89 4348.02,2046.89 4348.02,2066.89 4298.02,2066.89 4298.02,2046.89 ; 4298.02,2078.31 4348.02,2078.31 4348.02,2098.31 4298.02,2098.31 4298.02,2078.31 ; 4298.02,2123.63 4348.02,2123.63 4348.02,2143.63 4298.02,2143.63 4298.02,2123.63 ; 4399.23,253.8 4399.23,303.8 4419.23,303.8 4419.23,253.8 4399.23,253.8
M9 Title Sheet:
  drawing of 56 lines, arcs and shapes, not listed
  text "1" at 1060.93,13385.19 h70
  text "2" at 4386.59,13385.19 h70
  text "3" at 7716.59,13385.19 h70
  text "4" at 11051.59,13385.19 h70
  text "5" at 14376.59,13385.19 h70
  text "6" at 17711.59,13385.19 h70
  text "A" at -460.41,11607.19 h70
  text "A" at 19239.59,11607.19 h70
  text "B" at -460.41,7857.19 h70
  text "B" at 19239.59,7857.19 h70
  text "C" at -460.41,4107.19 h70
  text "C" at 19239.59,4107.19 h70
  text "D" at -460.41,357.19 h70
  text "D" at 19239.59,357.19 h70
  text "PROJECT TITLE:" at 16145.59,272.19 h45
  text ".PRJ_Title" at 16195.59,138.86 h70
  text "DESIGNED FOR:" at 16145.59,-28.81 h45
  text ".PRJ_Customer" at 16195.59,-168.81 h70
  text "FILE NAME:" at 16145.59,-328.81 h45
  text ".PCB_File_Name_No_Path" at 16195.59,-448.81 h70
  text "Texas Instruments (TI) and/or its licensors do not warrant the accuracy or completeness of this specification" at 11176.09,-610.65 h45
  text "ENGINEER:" at 16145.59,-618.81 h45
  text "LAYOUT BY:" at 17650.59,-618.81 h45
  text "or any information contained therein. TI and/or its licensors do not warrant that this design will meet" at 11131.11,-723.31 h45
  text ".PRJ_Engineer" at 16195.59,-773.8 h70
  text ".PCB_Layout" at 17701.09,-773.8 h70
  text "the specifications, will be suitable for your application or fit for any particular purpose, or will operate in" at 11131.11,-835.98 h45
  text ".Layer_Name" at 579.59,-854.69 h60
  text "ALTIUM DESIGNER VERSION:" at 17650.59,-928.81 h45
  text "an implementation. TI and/or its licensors do not warrant that the design is production worthy. You should" at 11131.11,-948.64 h45
  text "completely validate and test your design implementation to confirm the system functionality for your application." at 11176.09,-1061.31 h45
  text ".print_Scale" at 16195.59,-1062.14 h70
  text ".Application_BuildNumber" at 17701.09,-1062.14 h70
  text "1" at 1060.93,-1314.81 h70
  text "2" at 4386.59,-1314.81 h70
  text "3" at 7716.59,-1314.81 h70
  text "4" at 11051.59,-1314.81 h70
  text "5" at 14376.59,-1314.81 h70
  text "6" at 17711.59,-1314.81 h70
M10 Fab Notes:
  drawing of 213 lines, arcs and shapes, not listed
  text "M10 Fab Notes" at 16105.78,9542.79 h60
  text "DESIGN INFORMATION" at 17184.11,9425.67 h60
  text "MIN. TRACK WIDTH:" at 16539.55,9293.54 h60
  text "3" at 17635.8,9293.54 h60
  text "MIL" at 17790.55,9293.54 h60
  text "MIN. CLEARANCE:" at 16539.55,9169.42 h60
  text "MIL" at 17790.55,9169.42 h60
  text "4" at 17636.02,9167.78 h60
  text "MIN. VIA PAD SIZE:" at 16539.55,9045.29 h60
  text "18" at 17605.81,9045.29 h60
  text "MIL" at 17790.55,9045.29 h60
  text "0.05mm (2MIL)" at 17234.55,8915.39 h60
  text "MINIMUM ANNULAR RING" at 16210.32,8907.17 h60
  text "EXTERNAL" at 17942.55,8907.17 h60
  text "PER" at 16410.32,8797.04 h60
  text "IPC-D-275 CLASS 2 LEVEL C" at 16630.32,8797.04 h60
  text "MIL, HOLES" at 18118.55,8696.56 h60
  text "+/-" at 17726.09,8687.98 h60
  text "+/-" at 18580.09,8687.98 h60
  text "REGISTRATION TOLERANCES:" at 16210.32,8686.91 h60
  text "METAL" at 17410.09,8686.91 h60
  text "5" at 17986.3,8686.92 h60
  text "3" at 18819.3,8686.92 h60
  text "MIL" at 18935.55,8686.91 h60
  text "HOLE SIZE TOLERANCE (UNLESS OTHERWISE SPECIFIED):" at 16210.32,8588.6 h60
  text "+/-" at 18580.09,8585.72 h60
  text "3" at 18819.3,8584.66 h60
  text "MIL" at 18935.55,8584.66 h60
  text "MATERIAL:" at 16135.55,8447.01 h60
  text "UNIFORM STACKUP" at 17869.61,8352.09 h60
  text "HYBRID STACKUP" at 16844.07,8344.82 h60
  text "X" at 17720,8345 h60
  text "ISOLA FR4-370HR" at 16550.27,8181.17 h60
  text "Megtron 4    Isola I-Speed" at 16541.52,7979.92 h60
  text "OR" at 16991.52,7979.92 h60
  text "X" at 16407.1,7787.02 h60
  text "Megtron6    Isola MT-40    Nelco MW-1000" at 16541.52,7783.07 h60
  text "OR" at 16942.88,7783.07 h60
  text "OR" at 17641.6,7783.07 h60
  text "OTHER" at 16581.52,7586.22 h60
  text "X" at 18050,7390 h60
  text "62 MIL (1.6mm) +/-10%" at 16879.8,7388.64 h60
  text "78 MIL  +/-10%" at 18455.77,7388.64 h60
  text "THICKNESS:" at 16213.47,7380.42 h60
  text "OTHER" at 18164.7,7380.42 h60
  text "TOLERANCE:" at 16213.47,7242.1 h60
  text "X" at 17061.71,7242.1 h60
  text "ANSI IPC-6012 TYPE 3 CLASS 2" at 17239.72,7242.1 h60
  text "OTHER +/-" at 17239.7,7097.91 h60
  text "BOW & TWIST:" at 16213.47,6952.72 h60
  text "X" at 17061.71,6952.72 h60
  text "ANSI IPC-6012 TYPE 3 CLASS 2" at 17239.72,6952.72 h60
  text "OTHER +/-" at 17239.7,6806.03 h60
  text "DRILLING:" at 16138.7,6675.41 h60
  text "NC_DRILL FILES" at 17899.7,6570.22 h60
  text "REFERENCE:" at 16213.47,6566.28 h60
  text "X" at 16870.71,6566.19 h60
  text "AS SHOWN" at 17048.7,6566.28 h60
  text "X" at 17771.71,6566.28 h60
  text "OTHER" at 18197.7,6424.03 h60
  text "PTH COPPER THICKNESS:" at 16213.15,6420.5 h60
  text "X" at 17352.38,6420.5 h60
  text "20-30 um" at 17480.38,6420.5 h60
  text "BOARD FINISH:" at 16138.7,6272.9 h60
  text "SILKSCREEN:" at 16293.92,6162.78 h60
  text "X" at 17251.71,6162.78 h60
  text "TOP" at 17368.7,6162.78 h60
  text "X" at 17761.71,6162.78 h60
  text "BOTTOM" at 17879.7,6162.78 h60
  text "SILKSCREEN COLOR:" at 16293.92,6007.59 h60
  text "X" at 17251.71,6007.59 h60
  text "WHITE" at 17368.7,6007.59 h60
  text "OTHER" at 17879.7,6007.59 h60
  text "PURPLE" at 18485.49,5870.27 h60
  text "X" at 17974.38,5867.56 h60
  text "GREEN" at 17499.7,5864.14 h60
  text "OTHER" at 18117.7,5864.14 h60
  text "SOLDER RESIST COLOR:" at 16293.92,5857.27 h60
  text "X" at 17381.71,5709.89 h60
  text "MATTE" at 17499.7,5709.89 h60
  text "SEMI-GLOSS" at 18117.24,5709.25 h60
  text "X" at 17011.94,5537.12 h60
  text "IMMERSION GOLD (ENIG)" at 17199.7,5537.12 h60
  text "ENEPIG" at 18537.24,5529.9 h60
  text "SURFACE FINISH:" at 16138.7,5528.9 h60
  text "IMM. TIN/SILVER OR EQUIV" at 16468.24,5391.58 h60
  text "HARD GOLD (30u)" at 17899.7,5387.65 h60
  text "OTHER" at 16493.24,5190.79 h60
  text "ARRAY/PANEL:" at 16138.7,5035.42 h60
  text "CUT AND TRIM PER M1 BOARD OUTLINE" at 17199.7,5027.19 h60
  text "N.C. ROUTE" at 17199.7,4891.23 h60
  text "X" at 17887.71,4891.23 h60
  text "V. SCORE" at 18065.7,4891.23 h60
  text "CERTIFICATION:" at 16138.7,4762.1 h60
  text "MATERIALS AND WORKMANSHIP FOR ALL PCBS" at 16863.7,4762.1 h60
  text "TO MEET OR EXCEED THE REQUIREMENTS OF:" at 16863.7,4668.04 h60
  text "X" at 16501.21,4539.41 h60
  text "ANSI IPC-A-600F CLASS ->" at 16629.21,4539.41 h60
  text "X" at 18277.21,4539.41 h60
  text "2" at 18387.21,4539.41 h60
  text "1" at 18072.21,4537.91 h60
  text "3" at 18741.21,4537.91 h60
  text "X" at 17313.21,4391.72 h60
  text "RoHS" at 17441.21,4391.72 h60
  text "OTHER" at 18085.61,4391.72 h60
  text "PER ORDER" at 18482.66,4391.72 h60
  text "ALL BOARDS MUST MEET OR EXCEED UL94-V0 REQUIREMENTS." at 16166.24,4237.9 h60
  text "PCB MUST BEAR THE UL94V-0 UL REGISTERED MATERIAL ID NUMBER" at 16166.24,4121.83 h60
  text "ADDITIONAL REQUIREMENTS:" at 16138.7,3952.41 h60
  text "MICROSECTION:" at 16213.47,3845.28 h60
  text "YES" at 17119.21,3845.28 h60
  text "REQUIRED" at 17980.7,3700.95 h60
  text "BARE BOARD ELEC. TEST:" at 16213.47,3698.09 h60
  text "NONE" at 17519.21,3698.09 h60
  text "X" at 17862.71,3698.09 h60
  text "PER ORDER" at 18572.7,3698.09 h60
  text "FAB INSTRUCTIONS" at 16210.54,3407.09 h100
  text "X" at 16258,3255.88 h60
  text "16 MIL & SMALLER VIAS REQUIRE NON-CONDUCTIVE FILL AND PLANARIZE" at 16365.54,3167.09 h59
  text "X" at 16248,3060.88 h60
  text "OUTER LAYER TRACKS 12.1 MIL WIDE REQUIRE 50 OHM SINGLE-ENDED IMPEDANCE" at 16368.49,2956.46 h60
  text "X" at 16253,2845.88 h60
  text "TOP LAYER TRACKS 6.3 MIL WIDE WITH 4 MIL SPACE REQUIRE 100 OHM DIFFERENTIAL IMPEDANCE" at 16368.49,2751.73 h60
  text "X" at 16263,2645.88 h60
  text "BOTTOM LAYER TRACKS 5.6 MIL WIDE WITH 3.5 MIL SPACE REQUIRE 100 OHM DIFFERENTIAL IMPEDANCE" at 16363.49,2546.73 h60
  text "X" at 16253,2440.88 h60
  text "INNER LAYER TRACKS 3 MIL WIDE WITH   / 4 MIL SPACE REQUIRE 100 OHM DIFFERENTIAL IMPEDANCE" at 16362.59,2353.11 h60
  text "X" at 16263,2230.88 h60
  text "NO PULL-BACK ON COPPER FEATURES TO EDGE OF THE BOARD" at 16359.64,2148.38 h60
  text ".Layer_Name" at 579.59,-854.69 h60
M11 Gerber Information:
  lines w10: -289.41,-926.37 6310.59,-926.37 ; -289.41,-723.03 6312.59,-723.03 ; -289.41,-519.7 -289.41,-1129.7 3715.59,-1129.7 6312.59,-1129.7 6312.59,-519.7 -288.91,-519.7 -288.91,-1129.7 1286.59,-1129.7 ; 2175.59,-1129.7 2175.59,-519.7 ; 3442.59,-723.03 3442.59,-519.7 ; 4282.59,-723.03 4282.59,-519.7 ; 4904.59,-1136.2 4904.59,-933.37
  text "ALL ARTWORK VIEWED FROM TOP SIDE" at -225.91,-651.87 h60
  text "BOARD #:" at 2250.59,-651.87 h60
  text ".PRJ_Number" at 2796.09,-651.87 h60
  text "REV:" at 3640.59,-651.87 h60
  text ".PCB_Rev" at 3932.09,-651.87 h60
  text "SVN REV:" at 4478.59,-651.87 h60
  text ".VersionControl_RevNumber" at 4984.59,-651.87 h60
  text "LAYER NAME =" at -225.91,-854.69 h60
  text "PLOT NAME =" at -225.91,-1060.54 h60
  text ".plot_File_Name" at 579.59,-1060.54 h60
  text "GENERATED    :" at 2252.59,-1060.54 h60
  text ".Print_Date" at 3122.09,-1060.54 h60
  text ".Print_Time" at 3851.09,-1060.54 h60
  text "TEXAS INSTRUMENTS" at 5115.59,-1060.54 h60
M12 Stackup:
  drawing of 919 lines, arcs and shapes, not listed
  text "Layer" at 9959.38,4035.5 h60
  text "Name" at 10369.29,4035.5 h60
  text "Material" at 12368.69,4035.5 h60
  text "Thickness" at 13228.46,4035.5 h60
  text "Constant" at 13878.29,4035.5 h60
  text "Board Layer Stack" at 14448.15,4035.5 h60
  text "Top Overlay" at 10369.29,3915.5 h60
  text "Top Solder" at 10369.29,3795.5 h60
  text "Solder Resist" at 12368.69,3795.5 h60
  text "0.50mil" at 13228.46,3795.5 h60
  text "3.5" at 13878.29,3795.5 h60
  text "1" at 9959.38,3675.5 h60
  text "Top Layer" at 10369.29,3675.5 h60
  text "1.40mil" at 13228.46,3675.5 h60
  text "Dielectric 1" at 10369.29,3555.5 h60
  text "Megtron6" at 12368.69,3555.5 h60
  text "5.70mil" at 13228.46,3555.5 h60
  text "3.23" at 13878.29,3555.5 h60
  text "2" at 9959.38,3435.5 h60
  text "L2 GND" at 10369.29,3435.5 h60
  text "CF-004" at 12368.69,3435.5 h60
  text "1.40mil" at 13228.46,3435.5 h60
  text "Dielectric 2" at 10369.29,3315.5 h60
  text "Megtron6" at 12368.69,3315.5 h60
  text "3.03mil" at 13228.46,3315.5 h60
  text "3.22" at 13878.29,3315.5 h60
  text "3" at 9959.38,3195.5 h60
  text "L3 PWR" at 10369.29,3195.5 h60
  text "CF-004" at 12368.69,3195.5 h60
  text "1.40mil" at 13228.46,3195.5 h60
  text "Dielectric 3" at 10369.29,3075.5 h60
  text "Megtron6" at 12368.69,3075.5 h60
  text "3.03mil" at 13228.46,3075.5 h60
  text "3.22" at 13878.29,3075.5 h60
  text "4" at 9959.38,2955.5 h60
  text "L4 GND" at 10369.29,2955.5 h60
  text "CF-004" at 12368.69,2955.5 h60
  text "1.40mil" at 13228.46,2955.5 h60
  text "Dielectric 4" at 10369.29,2835.5 h60
  text "Megtron6" at 12368.69,2835.5 h60
  text "3.03mil" at 13228.46,2835.5 h60
  text "3.22" at 13878.29,2835.5 h60
  text "5" at 9959.38,2715.5 h60
  text "L5 PWR" at 10369.29,2715.5 h60
  text "CF-004" at 12368.69,2715.5 h60
  text "1.40mil" at 13228.46,2715.5 h60
  text "Dielectric 5" at 10369.29,2595.5 h60
  text "Megtron6" at 12368.69,2595.5 h60
  text "3.03mil" at 13228.46,2595.5 h60
  text "3.22" at 13878.29,2595.5 h60
  text "6" at 9959.38,2475.5 h60
  text "L6 GND" at 10369.29,2475.5 h60
  text "CF-004" at 12368.69,2475.5 h60
  text "1.40mil" at 13228.46,2475.5 h60
  text "Dielectric 6" at 10369.29,2355.5 h60
  text "Megtron6" at 12368.69,2355.5 h60
  text "4.09mil" at 13228.46,2355.5 h60
  text "3.13" at 13878.29,2355.5 h60
  text "7" at 9959.38,2235.5 h60
  text "L7 SIG" at 10369.29,2235.5 h60
  text "CF-004" at 12368.69,2235.5 h60
  text "1.40mil" at 13228.46,2235.5 h60
  text "Dielectric 7" at 10369.29,2115.5 h60
  text "Megtron6" at 12368.69,2115.5 h60
  text "3.86mil" at 13228.46,2115.5 h60
  text "3.34" at 13878.29,2115.5 h60
  text "8" at 9959.38,1995.5 h60
  text "L8 GND" at 10369.29,1995.5 h60
  text "CF-004" at 12368.69,1995.5 h60
  text "1.40mil" at 13228.46,1995.5 h60
  text "Dielectric 8" at 10369.29,1875.5 h60
  text "Megtron6" at 12368.69,1875.5 h60
  text "3.03mil" at 13228.46,1875.5 h60
  text "3.22" at 13878.29,1875.5 h60
  text "9" at 9959.38,1755.5 h60
  text "L9 GND" at 10369.29,1755.5 h60
  text "CF-004" at 12368.69,1755.5 h60
  text "1.40mil" at 13228.46,1755.5 h60
  text "Dielectric 9" at 10369.29,1635.5 h60
  text "Megtron6" at 12368.69,1635.5 h60
  text "3.86mil" at 13228.46,1635.5 h60
  text "3.34" at 13878.29,1635.5 h60
  text "10" at 9959.38,1515.5 h60
  text "L10 SIG" at 10369.29,1515.5 h60
  text "CF-004" at 12368.69,1515.5 h60
  text "1.40mil" at 13228.46,1515.5 h60
  text "Dielectric 10" at 10369.29,1395.5 h60
  text "Megtron6" at 12368.69,1395.5 h60
  text "4.09mil" at 13228.46,1395.5 h60
  text "3.13" at 13878.29,1395.5 h60
  text "11" at 9959.38,1275.5 h60
  text "L11 GND" at 10369.29,1275.5 h60
  text "CF-004" at 12368.69,1275.5 h60
  text "1.40mil" at 13228.46,1275.5 h60
  text "Dielectric 11" at 10369.29,1155.5 h60
  text "Megtron6" at 12368.69,1155.5 h60
  text "3.03mil" at 13228.46,1155.5 h60
  text "3.22" at 13878.29,1155.5 h60
  text "12" at 9959.38,1035.5 h60
  text "L12 PWR" at 10369.29,1035.5 h60
  text "CF-004" at 12368.69,1035.5 h60
  text "1.40mil" at 13228.46,1035.5 h60
  text "Dielectric 12" at 10369.29,915.5 h60
  text "Megtron6" at 12368.69,915.5 h60
  text "3.03mil" at 13228.46,915.5 h60
  text "3.22" at 13878.29,915.5 h60
  text "13" at 9959.38,795.5 h60
  text "L13 GND" at 10369.29,795.5 h60
  text "CF-004" at 12368.69,795.5 h60
  text "1.40mil" at 13228.46,795.5 h60
  text "Dielectric 13" at 10369.29,675.5 h60
  text "Megtron6" at 12368.69,675.5 h60
  text "3.03mil" at 13228.46,675.5 h60
  text "3.22" at 13878.29,675.5 h60
  text "14" at 9959.38,555.5 h60
  text "L14 PWR" at 10369.29,555.5 h60
  text "CF-004" at 12368.69,555.5 h60
  text "1.40mil" at 13228.46,555.5 h60
  text "Dielectric 14" at 10369.29,435.5 h60
  text "Megtron6" at 12368.69,435.5 h60
  text "3.03mil" at 13228.46,435.5 h60
  text "3.22" at 13878.29,435.5 h60
  text "15" at 9959.38,315.5 h60
  text "L15 GND" at 10369.29,315.5 h60
  text "CF-004" at 12368.69,315.5 h60
  text "1.40mil" at 13228.46,315.5 h60
  text "Dielectric 15" at 10369.29,195.5 h60
  text "Megtron6" at 12368.69,195.5 h60
  text "5.70mil" at 13228.46,195.5 h60
  text "3.23" at 13878.29,195.5 h60
  text "16" at 9959.38,75.5 h60
  text "Bottom Layer" at 10369.29,75.5 h60
  text "1.40mil" at 13228.46,75.5 h60
  text "Board Layer Stack Bottom Solder" at 10369.29,-44.5 h60
  text "Solder Resist" at 12368.69,-44.5 h60
  text "0.50mil" at 13228.46,-44.5 h60
  text "3.5" at 13878.29,-44.5 h60
  text "Board Layer Stack Bottom Overlay" at 10369.29,-164.5 h60
  text "Total board thickness:" at 9959.38,-284.5 h60
  text "77.97mil" at 13228.46,-284.5 h60
  text ".Layer_Name" at 579.59,-854.69 h60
